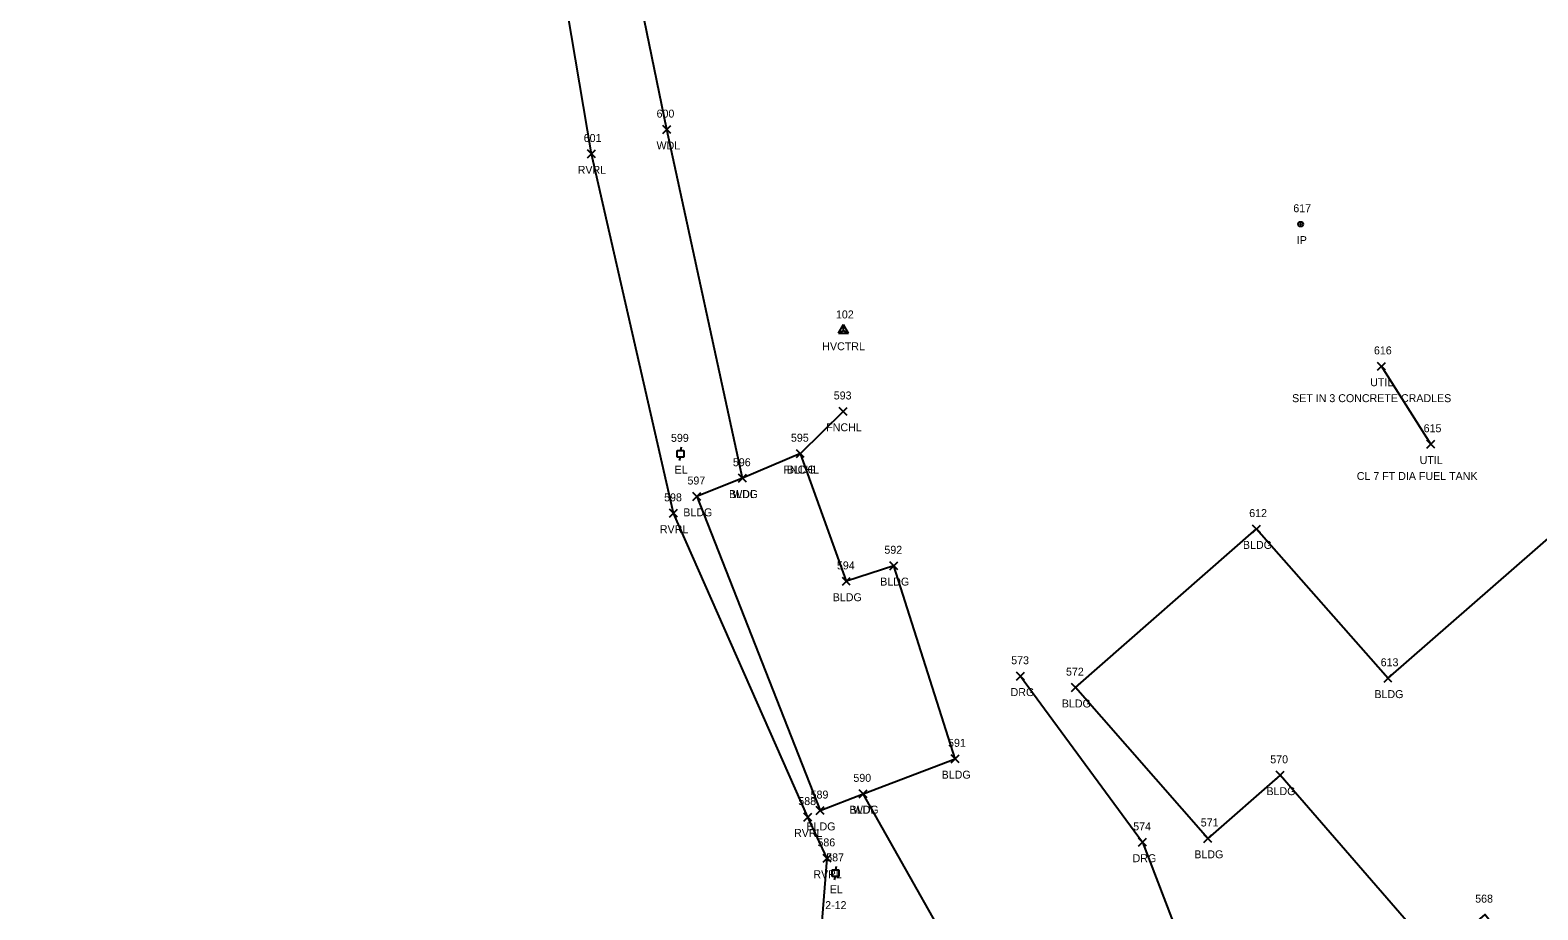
# Model space of a CAD drawing. Extents: x 1638029 to 1638889, y 618768 to 620505.
# Drawn here: x 1638091.2 to 1638469.9, y 619744.1 to 619965.1 of the extents above; entities that cross this region are included whole.
import ezdxf

# ---------------------------------------------------------------- set-up
doc = ezdxf.new("R2010")
doc.units = 0
for name, color, linetype in [('C_A', 7, 'Continuous'), ('C_I', 7, 'Continuous'), ('CPSM', 7, 'Continuous'), ('L_A', 7, 'Continuous'), ('L_I', 7, 'Continuous'), ('L_TIC', 7, 'Continuous'), ('LAWA', 7, 'Continuous'), ('LAWE', 7, 'Continuous'), ('LBC', 7, 'Continuous'), ('LFNC', 7, 'Continuous'), ('M_A', 7, 'Continuous'), ('M_I', 7, 'Continuous'), ('MPIR', 7, 'Continuous'), ('R_A', 7, 'Continuous'), ('R_I', 7, 'Continuous'), ('R_TIC', 7, 'Continuous'), ('RDG', 7, 'Continuous'), ('U_A', 7, 'Continuous'), ('U_C', 7, 'Continuous'), ('U_I', 7, 'Continuous'), ('UDEFAULT', 7, 'Continuous'), ('UEPT', 7, 'Continuous')]:
    doc.layers.add(name, color=color, linetype=linetype)

msp = doc.modelspace()

# ---------------------------------------------------------------- linework, layer by layer
at = {"layer": 'CPSM'}
for p, q in [((1638294.24, 619888.99), (1638295.49, 619891.15)), ((1638296.74, 619888.99), (1638295.49, 619891.15)), ((1638295.49, 619889.71), (1638295.49, 619891.15)), ((1638294.24, 619888.99), (1638295.49, 619889.71)), ((1638294.24, 619888.99), (1638296.74, 619888.99)), ((1638295.49, 619889.71), (1638295.49, 619889.71)), ((1638295.49, 619889.71), (1638296.74, 619888.99))]:
    msp.add_line(p, q, dxfattribs=at)
at = {"layer": 'L_TIC'}
for points in [[(1638250.15, 619939.17), (1638252.15, 619941.17)], [(1638252.15, 619939.17), (1638250.15, 619941.17)], [(1638231.19, 619933.04), (1638233.19, 619935.04)], [(1638233.19, 619933.04), (1638231.19, 619935.04)], [(1638294.43, 619868.35), (1638296.43, 619870.35)], [(1638296.43, 619868.35), (1638294.43, 619870.35)], [(1638283.68, 619857.73), (1638285.68, 619859.73)], [(1638285.68, 619857.73), (1638283.68, 619859.73)], [(1638283.68, 619857.73), (1638285.68, 619859.73)], [(1638285.68, 619857.73), (1638283.68, 619859.73)], [(1638269.16, 619851.57), (1638271.16, 619853.57)], [(1638271.16, 619851.57), (1638269.16, 619853.57)], [(1638269.16, 619851.57), (1638271.16, 619853.57)], [(1638271.16, 619851.57), (1638269.16, 619853.57)], [(1638257.69, 619846.98), (1638259.69, 619848.98)], [(1638259.69, 619846.98), (1638257.69, 619848.98)], [(1638251.82, 619842.75), (1638253.82, 619844.75)], [(1638253.82, 619842.75), (1638251.82, 619844.75)], [(1638398.26, 619838.8), (1638400.26, 619840.8)], [(1638400.26, 619838.8), (1638398.26, 619840.8)], [(1638307.15, 619829.58), (1638309.15, 619831.58)], [(1638309.15, 619829.58), (1638307.15, 619831.58)], [(1638295.23, 619825.65), (1638297.23, 619827.65)], [(1638297.23, 619825.65), (1638295.23, 619827.65)], [(1638431.28, 619801.31), (1638433.28, 619803.31)], [(1638433.28, 619801.31), (1638431.28, 619803.31)], [(1638352.77, 619798.96), (1638354.77, 619800.96)], [(1638354.77, 619798.96), (1638352.77, 619800.96)], [(1638322.58, 619781.07), (1638324.58, 619783.07)], [(1638324.58, 619781.07), (1638322.58, 619783.07)], [(1638404.16, 619776.93), (1638406.16, 619778.93)], [(1638406.16, 619776.93), (1638404.16, 619778.93)], [(1638299.45, 619772.27), (1638301.45, 619774.27)], [(1638301.45, 619772.27), (1638299.45, 619774.27)], [(1638299.45, 619772.27), (1638301.45, 619774.27)], [(1638301.45, 619772.27), (1638299.45, 619774.27)], [(1638288.63, 619768.07), (1638290.63, 619770.07)], [(1638290.63, 619768.07), (1638288.63, 619770.07)], [(1638285.53, 619766.43), (1638287.53, 619768.43)], [(1638287.53, 619766.43), (1638285.53, 619768.43)], [(1638386.04, 619761.06), (1638388.04, 619763.06)], [(1638388.04, 619761.06), (1638386.04, 619763.06)], [(1638290.39, 619756.05), (1638292.39, 619758.05)], [(1638292.39, 619756.05), (1638290.39, 619758.05)]]:
    msp.add_lwpolyline(points, dxfattribs=at)
at = {"layer": 'LAWA'}
for points in [[(1638270.16, 619852.57), (1638251.15, 619940.17), (1638239.8, 619995.3), (1638214.52, 620109.58), (1638175.21, 620188.68), (1638147.13, 620247.43), (1638107.71, 620276.84), (1638100.01, 620279.68)], [(1638338.56, 619691.01), (1638330.53, 619720), (1638300.45, 619773.27)]]:
    msp.add_lwpolyline(points, dxfattribs=at)
at = {"layer": 'LAWE'}
msp.add_lwpolyline([(1638288.08, 619714.92), (1638291.39, 619757.05), (1638286.53, 619767.43), (1638252.82, 619843.75), (1638232.19, 619934.04), (1638225.17, 619975.77), (1638193.81, 620114.82), (1638167.07, 620184.81), (1638143.16, 620243.98), (1638106.56, 620273.17), (1638091.23, 620278.21)], dxfattribs=at)
at = {"layer": 'LBC'}
for points in [[(1638289.63, 619769.07), (1638300.45, 619773.27), (1638323.58, 619782.07), (1638308.15, 619830.58), (1638296.23, 619826.65), (1638284.68, 619858.73), (1638270.16, 619852.57), (1638258.69, 619847.98)], [(1638258.69, 619847.98), (1638289.63, 619769.07)], [(1638538.14, 619765.89), (1638479.1, 619715), (1638456.59, 619742.92), (1638444.51, 619732.57), (1638405.16, 619777.93), (1638387.04, 619762.06), (1638353.77, 619799.96), (1638399.26, 619839.8), (1638432.28, 619802.31), (1638474.51, 619839.17)]]:
    msp.add_lwpolyline(points, dxfattribs=at)
at = {"layer": 'LFNC'}
msp.add_lwpolyline([(1638295.43, 619869.35), (1638284.68, 619858.73)], dxfattribs=at)
at = {"layer": 'MPIR'}
for radius in [0.625, 0.0833]:
    msp.add_circle((1638410.34, 619916.39), radius, dxfattribs=at)
at = {"layer": 'R_TIC'}
for points in [[(1638339, 619801.82), (1638341, 619803.82)], [(1638341, 619801.82), (1638339, 619803.82)], [(1638369.64, 619760.08), (1638371.64, 619762.08)], [(1638371.64, 619760.08), (1638369.64, 619762.08)]]:
    msp.add_lwpolyline(points, dxfattribs=at)
at = {"layer": 'RDG'}
msp.add_lwpolyline([(1638340, 619802.82), (1638370.64, 619761.08), (1638383.66, 619727.05), (1638374.72, 619691.97), (1638351.37, 619652.51), (1638328.65, 619642.9)], dxfattribs=at)
at = {"layer": 'UDEFAULT'}
for points in [[(1638429.65, 619879.67), (1638431.65, 619881.67)], [(1638431.65, 619879.67), (1638429.65, 619881.67)], [(1638443.07, 619861.11), (1638430.65, 619880.67)], [(1638442.07, 619860.11), (1638444.07, 619862.11)], [(1638444.07, 619860.11), (1638442.07, 619862.11)]]:
    msp.add_lwpolyline(points, dxfattribs=at)
at = {"layer": 'UEPT'}
for p, q in [((1638254.73, 619860.37), (1638254.56, 619859.54)), ((1638253.73, 619857.87), (1638253.73, 619859.54)), ((1638253.73, 619859.54), (1638255.4, 619859.54)), ((1638255.4, 619857.87), (1638253.73, 619857.87)), ((1638254.31, 619857.04), (1638254.56, 619857.87)), ((1638254.56, 619858.7), (1638254.56, 619858.7)), ((1638255.4, 619859.54), (1638255.4, 619857.87)), ((1638292.7, 619752.46), (1638292.7, 619754.13)), ((1638292.7, 619754.13), (1638294.37, 619754.13)), ((1638293.7, 619754.96), (1638293.54, 619754.13)), ((1638294.37, 619754.13), (1638294.37, 619752.46)), ((1638294.37, 619752.46), (1638292.7, 619752.46)), ((1638293.29, 619751.63), (1638293.54, 619752.46)), ((1638293.54, 619753.29), (1638293.54, 619753.29))]:
    msp.add_line(p, q, dxfattribs=at)

# ---------------------------------------------------------------- texts
at = {"layer": 'C_A'}
msp.add_text('HVCTRL', height=2, dxfattribs=at).set_placement((1638290.19, 619884.71))
at = {"layer": 'C_I'}
msp.add_text('102', height=2, dxfattribs=at).set_placement((1638293.62, 619892.71))
at = {"layer": 'L_A'}
for s, p in [('WDL', (1638248.56, 619935.17)), ('RVRL', (1638228.76, 619929.04)), ('FNCHL', (1638291.18, 619864.35)), ('FNCHL', (1638280.43, 619853.73)), ('BLDG', (1638281.28, 619853.73)), ('BLDG', (1638266.75, 619847.57)), ('WDL', (1638267.58, 619847.57)), ('BLDG', (1638255.28, 619842.98)), ('RVRL', (1638249.39, 619838.75)), ('BLDG', (1638395.85, 619834.8)), ('BLDG', (1638304.74, 619825.58)), ('BLDG', (1638292.82, 619821.65)), ('BLDG', (1638428.87, 619797.31)), ('BLDG', (1638350.36, 619794.96)), ('BLDG', (1638320.17, 619777.07)), ('BLDG', (1638401.75, 619772.93)), ('BLDG', (1638297.04, 619768.27)), ('WDL', (1638297.87, 619768.27)), ('BLDG', (1638286.22, 619764.07)), ('RVRL', (1638283.1, 619762.43)), ('BLDG', (1638383.63, 619757.06)), ('RVRL', (1638287.95, 619752.05))]:
    msp.add_text(s, height=2, dxfattribs=at).set_placement(p)
at = {"layer": 'L_I'}
for s, p in [('600', (1638248.57, 619943.17)), ('601', (1638230.27, 619937.04)), ('593', (1638293.07, 619872.35)), ('595', (1638282.32, 619861.73)), ('595', (1638282.32, 619861.73)), ('596', (1638267.74, 619855.57)), ('596', (1638267.74, 619855.57)), ('597', (1638256.33, 619850.98)), ('598', (1638250.46, 619846.75)), ('612', (1638397.42, 619842.8)), ('592', (1638305.79, 619833.58)), ('594', (1638293.87, 619829.65)), ('613', (1638430.44, 619805.31)), ('572', (1638351.41, 619802.96)), ('591', (1638321.78, 619785.07)), ('570', (1638402.71, 619780.93)), ('590', (1638298, 619776.27)), ('590', (1638298, 619776.27)), ('589', (1638287.26, 619772.07)), ('588', (1638284.17, 619770.43)), ('571', (1638385.25, 619765.06)), ('586', (1638288.97, 619760.05)), ('568', (1638454.18, 619745.92))]:
    msp.add_text(s, height=2, dxfattribs=at).set_placement(p)
at = {"layer": 'M_A'}
msp.add_text('IP', height=2, dxfattribs=at).set_placement((1638409.38, 619911.39))
at = {"layer": 'M_I'}
msp.add_text('617', height=2, dxfattribs=at).set_placement((1638408.49, 619919.39))
at = {"layer": 'R_A'}
for p in [(1638337.49, 619797.82), (1638368.13, 619756.08)]:
    msp.add_text('DRG', height=2, dxfattribs=at).set_placement(p)
at = {"layer": 'R_I'}
for s, p in [('573', (1638337.64, 619805.82)), ('574', (1638368.28, 619764.08))]:
    msp.add_text(s, height=2, dxfattribs=at).set_placement(p)
at = {"layer": 'U_A'}
for s, p in [('UTIL', (1638427.81, 619875.67)), ('UTIL', (1638440.23, 619856.11)), ('EL', (1638253.1, 619853.7)), ('EL', (1638292.07, 619748.29))]:
    msp.add_text(s, height=2, dxfattribs=at).set_placement(p)
at = {"layer": 'U_C'}
for s, p in [('SET IN 3 CONCRETE CRADLES', (1638408.19, 619871.67)), ('CL 7 FT DIA FUEL TANK', (1638424.44, 619852.11)), ('2-12', (1638290.92, 619744.29))]:
    msp.add_text(s, height=2, dxfattribs=at).set_placement(p)
at = {"layer": 'U_I'}
for s, p in [('616', (1638428.75, 619883.67)), ('599', (1638252.19, 619861.7)), ('615', (1638441.23, 619864.11)), ('587', (1638291.18, 619756.29))]:
    msp.add_text(s, height=2, dxfattribs=at).set_placement(p)

doc.saveas('drawing.dxf')
